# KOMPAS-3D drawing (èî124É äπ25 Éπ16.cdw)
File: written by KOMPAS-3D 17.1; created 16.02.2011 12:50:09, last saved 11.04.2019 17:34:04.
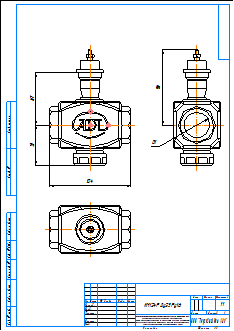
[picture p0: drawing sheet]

Title block, sheet 1: name: КМ124Р Ду25 Ру16; material: Внимание! Данный продукт является объектом авторского права ООО «Торговый Дом АДЛ». / Запрещается изменение, копирование, распространение / (в том числе путем копирования на другие сайты и ресурсы в Интернете) / или любое иное использование информации и объектов без предварительного / согласия правообладателя (ООО «Торговый Дом АДЛ»).; scale: 1:1; sheets: 1; organisation: ООО "Торговый дом АДЛ"; sheet format: A3; stored path: \\adlc.lan\data\АДЛ_ПКД\3D-модели\ADL production\Клапаны ГРАНРЕГ\Двухходовой клапан KM124P\KOMPAS 2D\КМ124Р Ду25 Ру16.cdw

Views: Спереди 1, Проекционный вид 2, Проекционный вид 3
Dimensions and other numbers on the sheet: 104; 51; 67; 96; 1:1; 1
